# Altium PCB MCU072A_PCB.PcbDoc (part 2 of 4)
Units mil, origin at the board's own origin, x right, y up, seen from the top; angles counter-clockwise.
Board outline 2661.1 x 1953.35 mil, 8 copper layers (Top Layer, Mid-Layer 2, Mid-Layer 3, Mid-Layer 4, Mid-Layer 5, Mid-Layer 6, Mid-Layer 7, Bottom Layer), stack 61.2 mil thick; 186 components, 165 nets, 716 pads, 419 vias.
Unrouted connection lines stored in the file: 1.
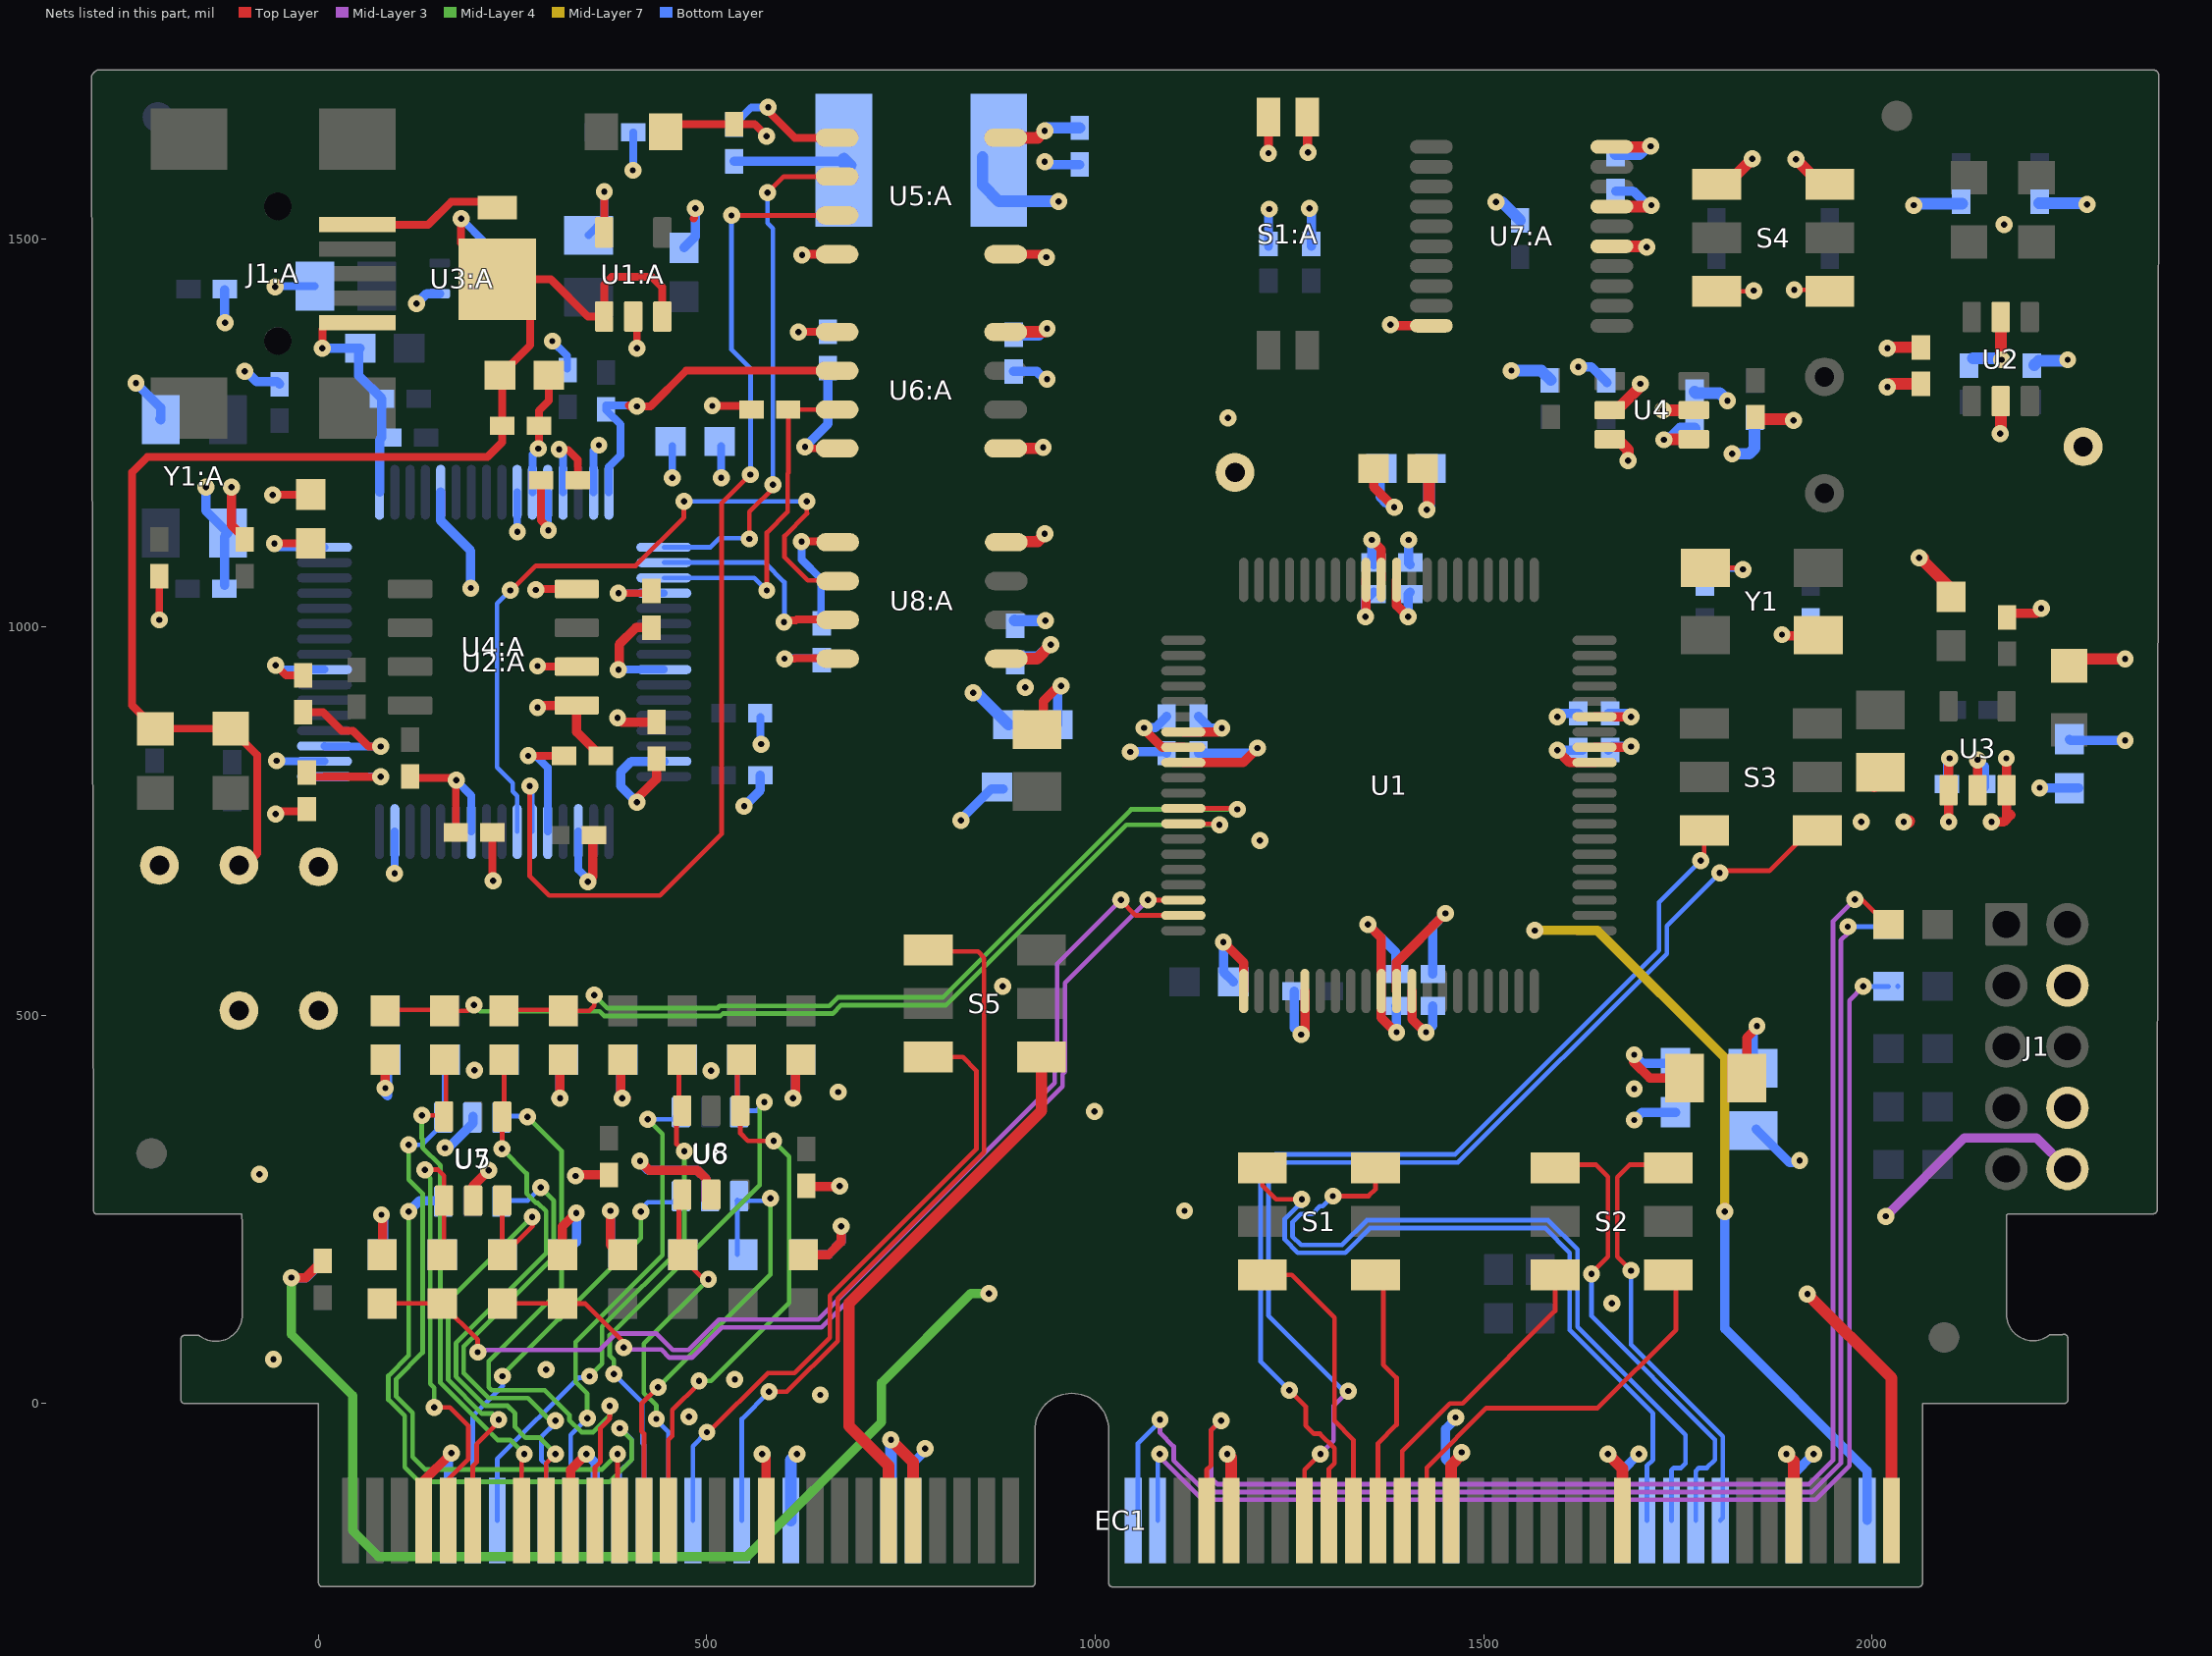
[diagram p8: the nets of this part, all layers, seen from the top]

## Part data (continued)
FID1 FID2 FID3 FID4 FID5 FID6: library part CMP-0077181-1, "Fiducial mark.  There is nothing to buy or mount.", Manufacturer=N/A
J1: library part CMP-0086568-1, "Board-To-Board Connector, TMM Series, 10 Contacts, Header, 2 mm, Through Hole, 2 Rows", Current_A=3.2A, Manufacturer=Samtec, Voltage_V=281V
J1:A: library part CMP-0054809-1, "Connector, Receptacle, USB Mini B 2.0, SMT", Color=Black, Current_A=1A, Manufacturer="Wurth Elektronik", Supplier Part Number 1=732-2109-1-ND, Voltage_V=30V
L1: library part CMP-0003363-1, "Ferrite Bead, 220 ohm @ 100 MHz, 2 A, 0805", Manufacturer=MuRata, Supplier Part Number 1=490-1054-1-ND, Value1="0.045 ohm", Value2=2A, ValueDisplayed="220 ohm"
L1:A L2:A: library part CMP-0003398-1, "Ferrite Bead, 600 ohm @ 100 MHz, 0.5 A, 0805", Manufacturer="Laird-Signal Integrity Products", Supplier Part Number 1=240-2399-1-ND, Value1="0.3 ohm", Value2=0.5A, ValueDisplayed="600 ohm"
L2: library part CMP-0003306-1, "Ferrite Bead, 60 ohm @ 100 MHz, 3 A, 0805", Manufacturer="Taiyo Yuden", Supplier Part Number 1=587-1932-1-ND, Value1="0.025 ohm", Value2=3A, ValueDisplayed="60 ohm"
LBL1: library part CMP-0003625-1, "Thermal Transfer Printable Labels, 0.650\" W x 0.200\" H - 10,000 per roll", Manufacturer=Brady, Supplier Part Number 1=97C5133
Logo1: library part CMP-0074844-1
Logo2: library part CMP-0074838-1, "Texas Instrument Corporate Signature"
Logo3: library part CMP-0074847-1, "FCC_disclaimer"
LOGO4: library part CMP-0074769-1
R1 R2: library part CMP-0026938-5, "RES, 4.7 k, 5%, 0.063 W, AEC-Q200 Grade 0, 0402", Manufacturer=Vishay-Dale, Power_W=63mW, Supplier Part Number 1=541-4.7KJCT-ND, TempCo="200 ppm/C", Tolerance_%=5%, Value2=0.063W, Value_Code=4k70, ValueDisplayed=4.7k
R1:A: library part CMP-0026962-3, "RES, 680, 5%, 0.063 W, AEC-Q200 Grade 0, 0402", Manufacturer=Vishay-Dale, Power_W=63mW, Supplier Part Number 1=541-680JCT-ND, TempCo="200 ppm/C", Tolerance_%=5%, Value2=0.063W, Value_Code=680R, ValueDisplayed=680
R2:A R4:A R8:A R15:A R16:A: library part CMP-0026825-5, "RES, 10 k, 5%, 0.063 W, AEC-Q200 Grade 0, 0402", Manufacturer=Vishay-Dale, Power_W=63mW, Supplier Part Number 1=541-10KJCT-ND, TempCo="200 ppm/C", Tolerance_%=5%, Value2=0.063W, Value_Code=10k0, ValueDisplayed=10k
R3 R4 R5 R6 R7 R8 R9 R10 R23 R24 R25 R26 R27 R28 R29 R30 R31 R32 R33 R34 R35 R36 R37 R38: library part CMP-0025697-4, "RES, 0, 5%, 0.1 W, AEC-Q200 Grade 0, 0603", Manufacturer=Vishay-Dale, Power_W=100mW, Supplier Part Number 1=541-0.0GCT-ND, TempCo="200 ppm/C", Tolerance_%=5%, Value2=0.1W, Value_Code=0000, ValueDisplayed=0
R3:A R11:A R12:A R14:A R20: library part CMP-0026822-3, "RES, 0, 5%, 0.063 W, AEC-Q200 Grade 0, 0402", Manufacturer=Vishay-Dale, Power_W=63mW, Supplier Part Number 1=541-0.0JCT-ND, TempCo="200 ppm/C", Tolerance_%=5%, Value2=0.063W, Value_Code=0000, ValueDisplayed=0
R5:A R6:A R7:A R10:A: library part CMP-0026852-3, "RES, 1.0 k, 5%, 0.063 W, AEC-Q200 Grade 0, 0402", Manufacturer=Vishay-Dale, Power_W=63mW, Supplier Part Number 1=541-1.0KJCT-ND, TempCo="200 ppm/C", Tolerance_%=5%, Value2=0.063W, Value_Code=1k00, ValueDisplayed=1.0k
R9:A R19 R21 R22: library part CMP-0026890-5, "RES, 2.2 k, 5%, 0.063 W, AEC-Q200 Grade 0, 0402", Manufacturer=Vishay-Dale, Power_W=63mW, Supplier Part Number 1=541-2.2KJCT-ND, TempCo="200 ppm/C", Tolerance_%=5%, Value2=0.063W, Value_Code=2k20, ValueDisplayed=2.2k
R11 R12: library part CMP-0026979-3, "RES, 820, 5%, 0.063 W, AEC-Q200 Grade 0, 0402", Manufacturer=Vishay-Dale, Power_W=63mW, Supplier Part Number 1=541-820JCT-ND, TempCo="200 ppm/C", Tolerance_%=5%, Value2=0.063W, Value_Code=820R, ValueDisplayed=820
R13 R14: library part CMP-0026863-2, "RES, 1.5 M, 5%, 0.063 W, AEC-Q200 Grade 0, 0402", Manufacturer=Vishay-Dale, Power_W=63mW, Supplier Part Number 1=541-1.5MJCT-ND, TempCo="200 ppm/C", Tolerance_%=5%, Value2=0.063W, Value_Code=1M50, ValueDisplayed=1.5M
R13:A: library part CMP-0026834-3, "RES, 12 k, 5%, 0.063 W, AEC-Q200 Grade 0, 0402", Manufacturer=Vishay-Dale, Power_W=63mW, Supplier Part Number 1=541-12KJCT-ND, TempCo="200 ppm/C", Tolerance_%=5%, Value2=0.063W, Value_Code=12k0, ValueDisplayed=12k
R15: library part CMP-0020442-3, "RES, 0, 5%, 0.125 W, AEC-Q200 Grade 0, 0805", Manufacturer=Vishay-Dale, Power_W=125mW, Supplier Part Number 1=541-0.0ACT-ND, TempCo="200 ppm/C", Tolerance_%=5%, Value2=0.125W, Value_Code=0000, ValueDisplayed=0
R16: library part CMP-0026944-3, "RES, 510, 5%, 0.063 W, AEC-Q200 Grade 0, 0402", Manufacturer=Vishay-Dale, Power_W=63mW, Supplier Part Number 1=541-510JCT-ND, TempCo="200 ppm/C", Tolerance_%=5%, Value2=0.063W, Value_Code=510R, ValueDisplayed=510
R17 R18: library part CMP-0026949-3, "RES, 56 k, 5%, 0.063 W, AEC-Q200 Grade 0, 0402", Manufacturer=Vishay-Dale, Power_W=63mW, Supplier Part Number 1=541-56KJCT-ND, TempCo="200 ppm/C", Tolerance_%=5%, Value2=0.063W, Value_Code=56k0, ValueDisplayed=56k
S1 S2 S4 S5: library part CMP-0002233-1, "Switch, Dual SPDT,  2 Pos, 0.1A, 6VDC, SMD", CurrentRating_mA=100A, Manufacturer="Copal Electronics", Supplier Part Number 1=CASD20JCT-ND
S1:A: library part CMP-0002230-1, "Switch, SPST, 2 Pos, 25mA, 24VDC, SMD", CurrentRating_mA=25A, Manufacturer="CTS Electrocomponents", Supplier Part Number 1=CT2182LPST-ND
S3: library part CMP-0002123-2, "SLIDE SWITCH DPDT  .1A, SMT", CurrentRating_mA=100A, Manufacturer="Copal Electronics", Supplier Part Number 1=CAS220JCT-ND
TP1 TP1:A TP2 TP2:A TP3 TP3:A TP4 TP5 TP6: library part CMP-0078143-3, "TEST POINT.  No entry in BOM.", Manufacturer=N/A
U1: library part CMP-0750188-2, "TMX320F280025CPNSR, PN0080A (LQFP-80)", Alternate Manufacturer="Texas Instruments"
U1:A: library part CMP-0073823-1, "Low-Noise, High PSRR, RF 200-mA Low-Dropout Linear Regulators, DBV0005A (SOT-23-5)", Alternate Manufacturer="Texas Instruments", Alternate PartNumber=TPS73033DBVT
U2: library part CMP-0051789-2, "Dual Buffer/Driver with Open-Drain Output, DBV0006A, LARGE T&R", F @ Nom Voltage(Max)(Mhz)=150, Generic Part Number=SN74LVC2G07, ICC @ Nom Voltage(Max)(mA)=0.01, Manufacturer="Texas Instruments", Operating Temperature Range(C)="-40 to 125", Rating=Catalog, tpd @ Nom Voltage(Max)(ns)=8.6,4.4,3.7,2.9, Voltage(Nom)(V)=1.8,2.5,3.3,5
U2:A: library part CMP-0004796-1, "Dual High Speed USB To Multipurpose UART/FIFO IC, LQFP-64", Manufacturer=FTDI, Supplier Part Number 1=768-1024-1-ND
U3: library part CMP-0036866-2, "Single Output Low Noise LDO, 400 mA, Fixed 3.3 V Output, 1.7 to 5.5 V Input, with Reverse Current Protection, 5-pin SOT-23 (DBV), -40 to 85 degC, Green (RoHS & no Sb/Br)", Alternate Manufacturer="Texas Instruments", Alternate PartNumber=TPS73633DBVT, Rating=Catalog
U3:A: library part CMP-0043096-2, "Low-Capacitance + / - 15 kV ESD-Protection Array for High-Speed Data Interfaces, 2 Channels, -40 to +85 degC, 5-pin SOT (DRL), Green (RoHS & no Sb/Br)", Breakdown Voltage(Min)(V)=11, IO Capacitance(Typ)(pF)=1.5, IO Leakage Current(nA)=1, Manufacturer="Texas Instruments"
U4: library part CMP-0067340-3, "High-Accuracy, Fixed-Threshold OV/UV Monitor, DDC0006A (SOT-23-T-6)", Alternate Manufacturer="Texas Instruments", Alternate PartNumber=TPS3702CX33DDCT
U4:A: library part CMP-0005261-2, "2K Microwire Compatible Serial EEPROM, SOIC-8", Manufacturer=Microchip, Supplier Part Number 1=93LC56C-I/SN-ND
U5 U6 U7 U8: library part CMP-0066599-1, "Automotive Low-Capacitance 4-Channel +/-15-kV ESD Protection Array for High-Speed Data Interfaces, DBV0006A (SOT-23-6)", Alternate Manufacturer="Texas Instruments"
U5:A U6:A U8:A: library part CMP-0029375-1, "25 Mbps Dual Channels, 2 / 0, Digital Isolator, 3.3 V / 5 V, -40 to +125 degC, 8-pin SOIC (D), Green (RoHS & no Sb/Br)", Insulation Rating(VRMS)=2500, Manufacturer="Texas Instruments", Rating=Catalog, Supply Voltage(s)(V)="3.3, 5"
U7:A: library part CMP-0047070-3, "Octal Buffer/Driver With 3-State OUtputs, PW0020A (TSSOP-20)", Alternate Manufacturer="Texas Instruments", Alternate PartNumber=SN74ALVC244PW, F @ Nom Voltage(Max)(Mhz)=100, Generic Part Number=SN74ALVC244, ICC @ Nom Voltage(Max)(mA)=0.024, Operating Temperature Range(C)="-40 to 85", Rating=Catalog, tpd @ Nom Voltage(Max)(ns)=4.4,3.1,2.8, Voltage(Nom)(V)=1.8,2.5,2.7,3.3
Y1: library part CMP-0080365-2, "Crystal, 20 MHz, 25 ppm, 18 pF, SMD", Frequency_Fixed=20MHz, Frequency Stability="30 ppm", Frequency Tolerance="25 ppm", Load Capacitance="18 pF", Manufacturer="ECS Inc.", Supplier Part Number 1=XC2693CT-ND
Y1:A: library part CMP-0004646-3, "Crystal, 12 MHz, 20pF, SMD", Frequency Stability=+/-50ppm, Manufacturer="ECS Inc.", PartNumber=ECS-120-20-30B-TR, Supplier Part Number 1=XC1118CT-ND
ZZ1: library part CMP-0003616-3
ZZ2: library part CMP-0077236-1
ZZ3: library part CMP-0077237-1
ZZ4: library part CMP-0077238-1

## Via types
v1: diameter 22, hole 8, Top Layer to Bottom Layer, tented both sides, 419 vias

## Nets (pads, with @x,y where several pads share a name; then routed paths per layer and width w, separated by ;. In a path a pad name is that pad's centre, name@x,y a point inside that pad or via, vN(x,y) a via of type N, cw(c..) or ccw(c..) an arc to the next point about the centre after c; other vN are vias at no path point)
3V3: C7.2 C9.1 C10.2 C20:A.1 C22:A.1 C23:A.2 C25.1 C25:A.1 EC1.119 J1.10 L1.1 L2.1 R1.1 R2.2 R11.2 R12.2 R13.2 R14.2 R15.2 R15:A.2 R16:A.2 R19.2 R21.2 R22.2 S4.1 S4.4 TP2.1 U2.5 U4.3 U4.4 U4.5 U5:A.8 U6:A.8 U7:A.20 U8:A.1 | length 3630.4
  Top Layer w12: v1(-35,162) -16.31,162 R1.1@5.31,183.62 ; L2.1@933.1,871.4 933.1,904.1 v1@949,920 ; L1.1@1839,419 1839,471 v1@1853,485
  Top Layer w15: U8:A.1@883.5,959.87 U8:A.1@885.5,959.87 ; U6:A.8@883.5,1379.87 933.87,1379.87 v1(938,1384) ; U5:A.8@883.5,1629.87 925.87,1629.87 v1(935,1639) ; U8:A.1@885.5,959 925,959 v1(943,977) ; U7:A.20@1662.34,1618 1714,1618 v1(1715,1619) ; U4.3@1662.47,1241.7 1672.3,1241.7 1686,1228 v1(1686,1214) ; v1@1731,1243 1731,1242 1731.3,1241.7 U4.4@1770.73,1241.7 ; v1(1731,1279) 1732,1279 1732.1,1279.1 U4.5@1770.73,1279.1 ; S4.1@1800.17,1569.93 1812.93,1569.93 v1(1846,1603) ; v1(1902.26,1602) 1934.33,1569.93 S4.4@1945.83,1569.93 ; v1(1917,141) 2025.31,32.69 EC1.119@2025.31,-150.67 ; R15.2@2003.24,794.76 R15.2@2003.24,809.76 ; v1(2020,1359) 2021.02,1360.02 C9.1@2063.1,1360.02 ; v1(2041,749) v1@2047.47,749 ; v1@2047.24,748.76 v1@2047.47,749 ; v1@2048.24,749.76 v1@2047.47,749 ; U2.5@2165.91,1399 2165.91,1347.09 v1@2167,1346
  Mid-Layer 3 w12: v1(2018,241) 2119,342 2211.73,342 J1.10@2251.74,302 ; J1.10@2248,302 J1.10@2251.74,302 ; J1.10@2251.84,301.89 J1.10@2251.74,302
  Mid-Layer 4 w12: v1(-35,162) -35,89 44,10 44,-164 77,-197 552,-197 725,-24 725,26.54 840.09,141.63 v1(863.24,141.63)
  Bottom Layer w12: v1(-35,162) -15.77,162 R2.2@5.51,183.28 ; C10.2@951.5,874 951.5,919.5 v1(956,924) ; R15:A.2@1223.1,1490.02 R15:A.2@1223.1,1493.02 1223.1,1537.1 v1(1224,1538) ; v1(1276,1539) 1278.1,1536.9 R16:A.2@1278.1,1493.02 R16:A.2@1278.1,1490.02 ; C7.2@1847.1,431.4 1847.1,481.1 v1(1852,486)
  Bottom Layer w15: C22:A.1@895,1376.24 927.24,1376.24 935,1384 v1(938,1384) ; C23:A.2@896.22,961.24 927.24,961.24 v1(943,977) ; v1(935,1639) 938.62,1642.62 C20:A.1@980,1642.62 ; v1(1516,1547) 1523.62,1547 R22.2@1547,1523.62 ; v1(1535.86,1330) 1574.32,1330 R19.2@1586.6,1317.72 ; C25:A.1@1670,1608.62 1700.62,1608.62 v1@1710,1618 ; v1@1731,1243 1741,1243 1753.48,1255.48 C25.1@1771.6,1255.48 ; v1(1820,1223) 1842,1223 1849,1230 R21.2@1849,1269.38 ; v1(2054,1543) 2055.86,1544.86 R11.2@2116.35,1544.86 ; R13.2@2130.23,1345.79 2165.21,1345.79 v1(2167,1344) ; R14.2@2209,1337 2214.62,1342.62 2250.62,1342.62 v1(2252,1344) ; R12.2@2215.08,1545.37 2275.63,1545.37 v1(2277,1544)
  other v1: 1986.24,748.76 910,922 1732,1241
EMU_1V8: C5:A.2 C6:A.2 C7:A.2 C8:A.2 U2:A.12 U2:A.37 U2:A.49 U2:A.64 | length 609.2
  Top Layer w10: v1(-56.72,1107.35) C5:A.2@-19.8,1107.35 ; C7:A.2@-17.19,809.68 -14.33,806.82 62.58,806.82 ; 7.72,807.23 62.17,807.23 62.58,806.82 ; v1(80,807) 62.77,807 62.58,806.82 ; v1(270,834) C8:A.2@316.38,834 ; C6:A.2@286.57,1188.84 286.57,1137.06 295.88,1127.75 v1(295.88,1124.55) v1@295.12,1125.31
  Bottom Layer w10: v1(-56.72,1107.35) -55.68,1108.38 -55.68,1105.68 -52.5,1102.5 U2:A.64@7.72,1102.5 ; U2:A.49@7.72,807.23 79.77,807.23 v1(80,807) ; v1(270,834) 280,834 295.12,818.88 U2:A.37@295.12,736.36 ; v1@295.12,1125.31 U2:A.12@295.12,1173.37
EMU_3V3: C2:A.1 C9:A.2 C10:A.2 C11:A.2 C12:A.2 C19:A.2 C21:A.2 C24:A.2 L1:A.2 L2:A.2 R1:A.1 R2:A.2 R4:A.2 R8:A.1 R10:A.1 TP2:A.1 U1:A.5 U2:A.20 U2:A.31 U2:A.42 U2:A.50 U2:A.56 U4:A.6 U4:A.8 U5:A.1 U6:A.1 U8:A.8 | length 1575.2
  Top Layer w10: v1(-55.01,950.64) -41.83,937.46 C10:A.2@-19.8,937.46 ; R8:A.1@112.18,805.44 174.32,805.44 v1(177.31,802.45) 176.73,801.87 C12:A.2@176.73,735.34 ; v1@281.2,1048.84 U4:A.8@332.48,1048.84 ; v1@282.79,948.84 U4:A.6@332.48,948.84 ; v1(367.99,1560.64) 367.79,1560.44 U1:A.5@367.79,1507.98 U1:A.5@371.93,1503.84 ; v1(386.22,1043.45) C9:A.2@425.79,1043.45 ; v1(506.99,1284.64) 552.37,1284.64 R2:A.2@552.6,1284.87 ; v1@576.5,1666.5 613.13,1629.87 U5:A.1@668.94,1629.87 ; v1(600,959) 612.6,959 613.61,960.02 ; v1@617.22,1379.87 U6:A.1@655.6,1379.87 ; v1(617.99,1379.64) 655.37,1379.64 U6:A.1@655.6,1379.87 ; U8:A.8@646.99,960.02 613.61,960.02 ; U6:A.1@655.99,1380.26 U6:A.1@655.6,1379.87 ; U8:A.8@668.94,959.87 613.76,959.87 613.61,960.02 ; U6:A.1@668.94,1379.87 U6:A.1@655.6,1379.87
  Top Layer w12: v1(410,774) 410,779 435.2,804.2 C11:A.2@435.2,830.22
  Bottom Layer w10: v1(-56.01,1437.64) -54.8,1438.84 L2:A.2@-4.8,1438.84 ; v1@-55,829 -52.91,826.91 U2:A.50@7.72,826.91 ; v1(-55.01,950.64) -49.37,945 U2:A.56@7.72,945.02 ; v1@177.31,802.26 196.69,782.88 U2:A.42@196.69,736.36 ; v1(301.07,1368.04) 320.2,1348.91 R10:A.1@320.2,1332.46 ; L1:A.2@347.57,1504.29 367.99,1524.71 v1(367.99,1560.64) ; v1(386.22,1043.45) U2:A.20@444.72,1043.45 ; v1@405.09,1588.32 R1:A.1@405.09,1636.91 ; v1(518.49,1192.13) C2:A.1@518.49,1232.64 ; C19:A.2@535,1646.62 557.38,1669 v1(579,1669) v1@580.62,1669 ; v1@568.82,854.81 R4:A.2@568.82,883.84 ; v1(600,959) 601.02,960.02 C24:A.2@646.99,960.02 ; v1(617.99,1379.64) 618.61,1380.26 C21:A.2@655.99,1380.26
  Bottom Layer w12: v1(410,774) 389.03,794.97 389.03,813.03 402.91,826.91 U2:A.31@444.72,826.91
  other v1: -53.73,827.57 570,849 281.99,949.64 279.99,1047.64 404.72,1587.95
EMU_5V0: C1:A.2 C3:A.1 D1:A.1 D3:A.2 D4:A.2 TP1:A.1 U1:A.1 U1:A.3 U3:A.1 | length 1863.2
  Top Layer w10: TP1:A.1@-91,696 -79,708 -79,834.97 D4:A.2@-113.01,868.98 -209.63,868.98 D3:A.2@-209.8,868.8 -240,899 -240,1199 -220.22,1218.78 217.5,1218.78 236.57,1237.86 C1:A.2@236.57,1258.84 236.57,1320.97 C3:A.1@233.7,1323.84 272.69,1362.83 D1:A.1@272.69,1447.05 ; v1(183.66,1525.59) 183.66,1494.38 D1:A.1@230.2,1447.84 ; D1:A.1@214.72,1468.53 251.2,1468.53 D1:A.1@272.69,1447.05 ; U1:A.3@442.6,1399.71 442.6,1437.38 429.37,1450.61 377.57,1450.61 367.79,1440.84 U1:A.1@367.79,1399.71 346.9,1399.71 299,1447.6 272.69,1447.6 D1:A.1@272.69,1447.05
  Bottom Layer w10: v1(183.66,1525.59) 214.72,1494.52 U3:A.1@214.72,1468.53
EMU_GND: C1:A.1 C2:A.2 C3:A.2 C4:A.1 C5:A.1 C6:A.1 C7:A.1 C8:A.1 C9:A.1 C10:A.1 C11:A.1 C12:A.1 C13:A.2 C14:A.1 C15:A.2 C16:A.1 C17:A.1 C18:A.1 C19:A.1 C21:A.1 C24:A.1 C26:A.2 D2:A.1 J1:A.5 R5:A.2 R11:A.2 R12:A.1 R13:A.1 R14:A.1 TP3:A.1 U1:A.2 U2:A.1 U2:A.5 U2:A.10 U2:A.11 U2:A.13 U2:A.15 U2:A.25 U2:A.35 U2:A.47 U2:A.51 U3:A.4 U4:A.5 U5:A.4 U6:A.4 U8:A.5 Y1:A.2 Y1:A.4 | length 3014.3
  Top Layer w10: v1(-205,1009) -205,1065.02 C17:A.1@-204.8,1065.22 ; v1(-59,1170) -20.14,1170 C5:A.1@-19.8,1170.34 ; v1@-46.76,762.44 C7:A.1@-17.19,762.44 ; C10:A.1@-19.8,890.22 5.94,890.22 29.9,866.26 44.29,866.26 64.55,846 v1(80,846) ; v1(5,1359) 5,1383.06 13.82,1391.87 J1:A.5@49.86,1391.87 ; v1@98.14,682.03 v1@98.27,682.15 ; C12:A.1@223.98,735.34 223.98,674.55 v1@224.87,673.65 ; v1(282.99,1229.64) 283.82,1230.46 C1:A.1@283.82,1258.84 283.82,1278.46 296.69,1291.34 C3:A.2@296.69,1323.84 ; v1(309.8,1228.54) 310.63,1227.71 321.47,1227.71 333.82,1215.37 C6:A.1@333.82,1188.84 ; R14:A.1@352,733.84 R14:A.1@352,735 ; U1:A.2@405.2,1399.71 410,1394.9 v1(410,1359) ; D2:A.1@445,1639 453.46,1647.46 C4:A.1@531.46,1647.46 ; 482.79,1525.74 483.55,1526.5 ; C4:A.1@535,1651 C4:A.1@531.46,1647.46 ; v1(577,1632) 561.54,1647.46 C4:A.1@535.2,1647.46 C4:A.1@531.46,1647.46 ; v1(621.97,1109.87) U8:A.5@668.94,1109.87 ; v1(626.37,1231.85) 628.35,1229.87 U6:A.4@668.94,1229.87
  Top Layer w12: v1(-112,1180) -112,1131 R12:A.1@-95,1114 ; v1(282,896) 284.84,898.84 U4:A.5@332.48,898.84 332.48,864.52 C8:A.1@362,835 ; v1(347,672) 353,678 R14:A.1@353,735 ; C8:A.1@363.62,834 C8:A.1@363.62,835 ; v1(385,883) 390.54,877.46 C11:A.1@435.2,877.46 ; v1(386.22,944.87) 387.08,945.72 387.08,977.2 408.99,999.12 C9:A.1@428.7,999.12 ; v1(622.61,1479.03) 623.44,1479.87 U5:A.4@668.94,1479.87
  Bottom Layer w10: U2:A.51@7.72,846.6 8.31,846 v1(80,846) ; v1@98.27,682.15 U2:A.47@98.27,736.36 ; v1@255.75,1123.73 U2:A.10@255.75,1173.37 ; U2:A.11@275.43,1173.37 275.43,1222.08 v1(282.99,1229.64) ; v1(309.8,1228.54) 314.8,1223.54 U2:A.13@314.8,1173.37 ; U2:A.35@334.49,736.36 334.49,687.51 346,676 v1@346,671 ; U2:A.15@354.17,1173.37 354.17,1227.17 v1(361,1234) ; v1@386.22,945.02 U2:A.25@444.72,945.02 ; C2:A.2@455.5,1232.64 v1(455.5,1191.9) v1@455.95,1191.44 ; v1(621.97,1109.87) 621.97,1086.64 646.99,1061.61 C24:A.1@646.99,1007.26
  Bottom Layer w12: v1(-235,1314) -203.11,1282.11 Y1:A.2@-203.11,1266.68 Y1:A.2@-204.05,1267.61 ; v1(-145,1180) -145,1149.51 Y1:A.4@-116.5,1121.01 -121.18,1116.32 C14:A.1@-121.18,1053.84 ; R11:A.2@-121.18,1433.84 -121.18,1392.42 v1(-120.28,1391.52) ; v1(-95,1329) -93,1329 -80,1316 -53.38,1316 C18:A.1@-50,1312.62 ; v1(5,1359) 5.16,1358.84 C15:A.2@53.7,1358.84 51.93,1357.07 51.93,1323.49 C16:A.1@81.57,1293.84 81.57,1243.84 78.58,1240.85 U2:A.1@78.58,1173.37 ; v1(126.39,1416.23) 139.31,1429.16 U3:A.4@155.67,1429.16 ; U2:A.5@157.32,1173.37 157.32,1136.68 196,1098 v1(196,1050) ; v1@346,671 v1(347,672) ; C13:A.2@470.54,1488.14 485,1502.6 v1(485,1539) ; C19:A.1@535,1599.38 671.13,1599.38 676.61,1604.87 678.44,1603.04 687.05,1594.43 686.35,1593.74 676.21,1594.12 C26:A.2@676.14,1594.12 ; v1(548,769) 568.82,789.82 R5:A.2@568.82,808.84 ; v1(626.37,1231.85) 655.99,1261.48 C21:A.1@655.99,1333.02
  other v1: 224.68,673.27 97.99,682.5 -55,759 256.06,1122.28
EMU_SCI-RX: U2:A.38 U5:A.3 | length 1424.5
  Top Layer w6: v1(272,795) 272,678.88 296.88,654 439.53,654 518.89,733.36 518.89,1158.86 v1(556.16,1196.13) ; v1(531.76,1529.87) U5:A.3@668.94,1529.87
  Bottom Layer w6: v1@272,794 275.43,790.57 U2:A.38@275.43,736.36 ; v1(531.76,1529.87) 531.76,1357.03 556.16,1332.63 v1(556.16,1196.13)
EMU_SCI-TX: U2:A.39 U8:A.6 | length 936.4
  Top Layer w6: v1@247,1046 279.64,1078.64 408.39,1078.64 470.5,1140.75 v1(470.5,1161.77) ; v1(628.8,1161.77) 628.8,1145.8 ; 629,1146 628.8,1145.8 ; U8:A.6@668.94,1059.87 629.88,1059.87 600,1089.74 600,1117 628.8,1145.8
  Bottom Layer w6: v1(247,1047) 230,1030 230,819 250,799 250,788 255.75,782.25 U2:A.39@255.75,736.36 ; v1@470.17,1162.09 v1(470.5,1161.77) v1(628.8,1161.77)
EMU_TCK: R3:A.1 U2:A.16 U6:A.2 | length 455.1
  Top Layer w10: v1@399.41,1285.22 400.63,1284 v1(410,1284) 427.35,1284 473.22,1329.87 U6:A.2@668.94,1329.87
  Bottom Layer w10: U2:A.16@373.86,1173.37 373.86,1206.11 388.79,1221.04 388.79,1260.75 370.2,1279.34 370.2,1285.22 408.78,1285.22 v1(410,1284)
EMU_TDI: U2:A.17 U5:A.2 | length 679.2
  Top Layer w6: v1(554.73,1113.33) 554.73,1148.05 588,1181.32 586.32,1183 v1(585,1183) ; v1(578,1559) 598.87,1579.87 U5:A.2@667.72,1579.87 U5:A.2@668.94,1579.87
  Bottom Layer w6: U2:A.17@444.72,1102.5 504.41,1102.5 516.1,1114.19 553.87,1114.19 v1(554.73,1113.33) ; v1(578,1559) 578,1520 585,1513 v1(585,1183)
EMU_TDO: U2:A.18 U8:A.7 | length 287.4
  Top Layer w10: v1(599.25,1006.09) 601.73,1008.58 614.42,1008.58 615.71,1009.87 U8:A.7@668.94,1009.87
  Bottom Layer w6: U2:A.18@444.72,1082.82 574.74,1082.82 599.9,1057.66 v1@599.9,1007.08
EMU_TMS: R2:A.1 U2:A.19 U6:A.3 | length 447.8
  Top Layer w6: v1@577.31,1046.67 577.31,1121.38 604,1148.07 604,1197.77 604.84,1198.61 604.84,1279.87 U6:A.3@668.94,1279.87
  Bottom Layer w6: U2:A.19@444.72,1063.13 560.95,1063.13 v1(577.12,1046.96)
EMU_USB_5V0: D1:A.2 J1:A.1 | length 195.6
  Top Layer w10: J1:A.1@49.86,1517.86 141.21,1517.86 170.65,1547.3 222.74,1547.3 D1:A.2@230.2,1539.84
GND: C1.2 C2.2 C3.1 C4.1 C5.1 C6.1 C7.1 C8.2 C9.2 C10.1 C11.1 C12.2 C13.2 C14.2 C15.2 C16.2 C17.2 C18.2 C19.2 C20.2 C20:A.2 C21.1 C22.1 C22:A.2 C23.1 C23:A.1 C24.1 C25.2 C25:A.2 C26.2 C26:A.1 C27.2 C28.1 C29.2 C30.2 C31.2 C32.2 C33.2 C34.2 C35.2 C36.2 C37.2 C38.2 C39.2 C40.2 C41.2 C42.2 C43.2 C44.2 D3.1 EC1.7 EC1.10 EC1.19 EC1.22 EC1.35 EC1.38 EC1.46 EC1.47 EC1.65 EC1.83 EC1.97 EC1.111 J1.4 J1.8 S1:A.3 S1:A.4 S4.3 S4.6 TP4.1 U1.9 U1.21 U1.25 U1.30 U1.55 U1.70 U2.2 U3.2 U4.2 U5.2 U5:A.5 U6.2 U6:A.5 U7.2 U7:A.10 U7:A.15 U7:A.17 U8.2 U8:A.4 Y1.2 Y1.4 | length 5460.8
  Top Layer w6: Y1.2@1785.5,1076.13 1831.87,1076.13 v1(1834,1074) ; S4.3@1800.17,1432.13 1847.13,1432.13 v1(1848,1433) ; v1(1900,1434) 1943.97,1434 S4.6@1945.83,1432.13
  Top Layer w12: v1(81,243) 82.9,241.1 C29.2@82.9,192.1 ; v1(86,406) C31.2@86,442.5 ; EC1.7@135.55,-150.67 135.55,-99.45 v1(171,-64) ; U5.2@199.1,261.27 199.1,280.1 v1(219,300) v1@220,299 ; v1(311,393) C32.2@311,445.01 ; C30.2@314.1,191.9 C30.2@314.1,194.9 ; C30.2@316,193 C30.2@314.1,194.9 ; EC1.19@324.53,-150.67 324.53,-85.47 v1(345,-65) ; v1@327,291 330.38,294.38 C27.2@376,294.38 ; v1@333,247 314.1,228.1 C30.2@314.1,194.9 ; v1(376,248) 376,204 C39.2@387,193 ; C41.2@389.1,443.9 389.1,399.9 v1@396,393 ; v1(414,312) 426,300 488,300 499.1,288.9 U8.2@499.1,261.27 ; v1(571,-65) 576.49,-70.49 EC1.35@576.49,-150.67 ; v1(611,393) 614.1,396.1 C36.2@614.1,443.9 ; C37.2@624,191.5 656.5,191.5 673,208 v1(673,228) ; C26.2@626,279.38 664.62,279.38 665.25,280 v1(671,280) ; U5:A.5@883.5,1479.87 933.13,1479.87 v1(937,1476) ; U1.9@1113.45,825.29 1190.29,825.29 v1(1209,844) ; v1(1165,594) 1191.2,567.8 U1.21@1191.2,531 ; v1(1223,1610) 1223.1,1610.1 S1:A.4@1223.1,1656.4 ; v1(1265,475) 1269.94,479.94 U1.25@1269.94,531 ; S1:A.3@1273.1,1656.4 1273.1,1611.9 v1(1274,1611) ; v1(1351,617) 1368.37,599.63 U1.30@1368.37,531 1368.37,496.63 1387,478 v1(1388.06,478) ; v1(1380,1389) 1381.32,1387.68 U7:A.10@1430.05,1387.68 ; U1.70@1388.06,1060.53 1388.06,1027.94 v1(1403,1013) ; U1.55@1642.98,884.35 v1(1690,884.35) ; v1@1882.64,988.52 Y1.4@1931.17,988.52 ; U3.2@2136,789.63 v1(2136,828.76) ; C21.1@2176,1017.39 2211.62,1017.39 v1(2218,1023.76)
  Top Layer w15: v1(737,-47) 765.47,-75.47 EC1.47@765.47,-150.67 ; U8:A.4@883.5,1109.87 925.87,1109.87 935,1119 v1(935,1120) ; U6:A.5@883.5,1229.87 931.87,1229.87 v1(933,1231) ; v1(1170,-65) 1174.92,-69.92 EC1.65@1174.92,-150.67 ; v1@1429.6,1159.6 C2.2@1429.6,1191.4 ; EC1.83@1458,-144.29 1458,-80 v1@1473,-64 ; v1(1660,-65) 1678.86,-83.86 EC1.97@1678.86,-150.67 ; U7:A.15@1662.34,1490.05 v1@1708.95,1490.05 ; U7:A.17@1662.34,1541.23 1714.23,1541.23 v1(1716,1543) ; U4.2@1662.47,1279.1 1671.65,1279.1 1702,1309.45 v1(1702,1313) ; C24.1@1854,1267.38 v1@1897.62,1267.38 ; v1(1890,-65) 1899.33,-74.33 EC1.111@1899.33,-150.67 ; v1(2020,1309) 2023.78,1312.78 C9.2@2063.1,1312.78 ; v1@2066,1088.76 2066,1085.26 C22.1@2106,1045.26 ; v1(2165,1249) 2165.91,1249.91 U2.2@2165.91,1290.73 ; D3.1@2254,949.98 2262.78,958.76 v1(2326,958.76)
  Bottom Layer w6: C18.2@1785,1055.62 1803.38,1074 v1(1834,1074) ; v1@1887,989 1901.62,989 C17.2@1921,1008.38 ; v1(1900,1434) v1@1900.62,1434.62
  Bottom Layer w12: v1(81,243) 84.1,239.9 C43.2@84.1,191.9 ; v1(86,406) 86,399.2 89.1,396.1 C34.2@89.1,443.9 ; v1(163,329) 165.63,329 v1@166.31,329.69 ; v1@167,329 199.1,361.1 U7.2@199.1,369.53 ; EC1.10@167.05,-150.67 167.05,-67.95 v1(171,-64) ; v1@306,393 v1@311,398 ; v1(311,393) v1@311,398 ; C33.2@311,445.01 v1@311,398 ; C42.2@315,191 332,208 v1(332,245) ; v1(345,-65) 356.02,-76.02 EC1.22@356.02,-150.67 ; v1(376,248) 376,205 C40.2@392,189 ; C44.2@389.1,443.9 389.1,394.9 v1(391,393) ; v1@412,313 425,300 488,300 499.1,288.9 U6.2@499.1,261.27 ; v1(611,393) 614.1,396.1 C38.2@614.1,443.9 ; C35.2@614.1,191.9 C35.2@623.93,191.9 ; C35.2@623.93,191.5 656.5,191.5 673,208 v1(673,228) ; v1(827,751) 827,752 866.4,791.4 C11.1@881.6,791.4 ; v1@843,914 v1(843,915) ; C22:A.2@895,1329 925,1329 935,1319 v1(938,1319) ; v1(935,1599) 938.62,1595.38 C20:A.2@980,1595.38 ; v1(1045,839) 1090.38,839 C6.1@1092,837.38 ; C12.2@1133,837.38 1202.38,837.38 v1(1209,844) ; v1(1165,594) 1165,555.99 C28.1@1177.99,543 ; C16.2@1256.38,531 1256.38,483.62 v1(1265,475) ; v1(1351,617) 1387.38,580.62 C5.1@1387.38,553 ; C13.2@1387.38,512 1388.06,511.32 v1(1388.06,478) ; v1(1403,1013) 1403,1042.38 C15.2@1405.62,1045 ; v1(1403.62,1112) 1403.62,1082 C3.1@1405.62,1080 ; v1(1595,884.35) 1599.28,888.62 C14.2@1622,888.62 ; v1(1622,1335) 1638.62,1335 C23.1@1659,1314.62 ; C4.1@1660.98,888.62 1685.72,888.62 v1(1690,884.35) ; C25:A.2@1670,1561.38 1692.62,1561.38 1711,1543 v1(1716,1543) ; v1(1694,365) 1703.9,374.9 C8.2@1747.1,374.9 ; C7.1@1851,353 1894,310 v1@1907,310 ; v1(2136,828.76) 2144.62,820.14 C20.2@2144.62,793.76 ; C19.2@2254,855.26 2255.5,853.76 v1(2326,853.76)
  Bottom Layer w15: EC1.38@607.99,-150.67 607.99,-73.01 v1(616,-65) ; EC1.46@737,-146.64 v1(737,-47) ; v1@840,914 843,914 848.5,914 C10.1@888.5,874 ; C26:A.1@854.96,1604.87 854.96,1569.04 876,1548 v1(953,1548) ; C23:A.1@896.22,1008.49 896.71,1008 v1(936,1008) ; v1@1428,1151 1430,1153 C1.2@1430,1196 ; C25.2@1771.6,1302.72 1773.32,1301 1804,1301 v1(1814,1291)
  other v1: 1472,-63 477,-17.26 646,11 536,31 293,43.63 -58,57 1665.14,129 1115,248 331,293 -76,295 1907,313 999,376 669,401 505.64,428.5 201,429 881,537 1212,725 1884.16,990 2061,1088.76 1427,1151 1899,1266 1171,1269 1710,1489 2170,1518
HSEC_5V0: C19.1 C20.1 EC1.48 EC1.84 EC1.98 EC1.112 TP1.1 U3.1 U3.3 | length 713.5
  Top Layer w12: v1@2099,752.76 2098.6,753.17 2098.6,831.36 2099.2,830.76 v1(2100,830.76) ; v1(2154,748.76) 2169.8,748.76 2178.8,757.76 2176.8,759.76 2173.4,756.36 2173.4,829.36 v1@2172,830.76
  Bottom Layer w12: EC1.48@765.47,-150.67 765.47,-76.53 781,-61 v1(781,-58.1) ; EC1.84@1458.38,-150.67 1458.38,-79.08 1451,-71.7 1451,-33 1464,-20 v1(1464,-18) ; EC1.98@1678.86,-150.67 1678.86,-86.14 v1(1700,-65) ; EC1.112@1899.33,-150.67 1899.33,-90.67 v1(1925,-65) ; C20.1@2097.38,793.76 2097.38,830.14 2098.76,828.76 2100,830.01 v1(2100,830.76) ; v1(2216,792.76) 2253.5,792.76 C19.1@2254,792.27 C19.1@2266,792.27
  other v1: 2099,748.76 2173,830.76
HSEC_A0/C15: EC1.9 R23.2 U5.1 | length 636.9
  Top Layer w6: v1(137,301) 154,301 161.7,293.3 161.7,203.1 166,198.8 R23.2@159.1,191.9 ; v1(149,-5) 169,-5 193,-29 193,-71.46 167.05,-97.41 EC1.9@167.05,-150.67
  Mid-Layer 4 w6: v1(137,301) 133,301 144,290 144,25.29 149,20.29 v1(149,-5)
HSEC_A1: EC1.11 R24.2 U5.3 | length 620.4
  Top Layer w6: EC1.11@198.54,-150.67 198.54,-81 203.54,-76 203.54,-52.46 v1@237,-19 ; R24.2@236,193 236.5,193.5 U5.3@236.5,261.27 ; R24.2@239.1,191.9 276,228.8 275,229.8 v1(275,240)
  Mid-Layer 4 w6: v1(232,-21) 224,-13 210.57,-13 167,30.57 167,132 v1(275,240)
HSEC_A2/C9: EC1.15 R25.2 U5.6 | length 690.6
  Top Layer w6: v1(133,371) 160.23,371 U5.6@161.7,369.53 ; U5.6@162,371 164.1,373.1 R25.2@164.1,443.9 ; EC1.15@261.53,-150.67 261.53,-68.47 v1(265,-65)
  Mid-Layer 4 w6: v1(133,371) 133,341.46 134,340.46 134,329.46 157,306.46 157,26.43 230.43,-47 247,-47 v1(265,-65)
HSEC_A3/C5/VDAC: EC1.17 R26.2 U5.4 | length 755
  Top Layer w6: v1(236,328) 236.5,328.5 U5.4@236.5,369.53 ; U5.4@239.1,368.1 R26.2@239.1,443.9 ; EC1.17@293.03,-150.67 293.03,-76.97 v1(305,-65)
  Mid-Layer 4 w6: v1(236,328) 268,296 268,270.54 280.54,258 282.46,258 293,247.46 293,193.6 177,77.6 177,34.72 214.72,-3 243.46,-3 253,-12.54 253,-30.46 266.54,-44 285,-44 v1@306,-65
HSEC_A4/C14: EC1.21 R27.2 U7.3 | length 883.7
  Top Layer w6: EC1.21@356.02,-150.67 356.02,-81.98 363,-75 363,-31.54 375,-19.54 v1(375,-3)
  Mid-Layer 4 w6: v1(269,369) 313,325 313,148.54 219,54.54 219,21 223,17 291.46,17 323,-14.54 323,-21.46 338.54,-37 353.46,-37 375,-15.46 v1(375,-3)
  Bottom Layer w6: R27.2@239.1,443.9 239.1,439.1 239.1,373.1 236,370 v1@268,370
  Bottom Layer w12: R27.2@236.5,436.5 239.1,439.1 241,441 R27.2@241,445
HSEC_A5/C2: EC1.23 R28.2 U7.1 | length 936.9
  Top Layer w6: v1(385,-65) 385,-148.15 EC1.23@387.52,-150.67
  Mid-Layer 4 w6: v1(116,333) 116,288.46 134,270.46 134,65.46 100,31.46 100,9 121,-12 121,-69 137,-85 365,-85 v1(385,-65)
  Bottom Layer w6: v1@117,333 133,333 161.7,361.7 R28.2@161.7,439.3
  Bottom Layer w12: R28.2@159,443 159,442 R28.2@161.7,439.3
HSEC_A6: EC1.25 R29.2 U6.1 | length 604.3
  Top Layer w6: EC1.25@419.01,-150.67 419.01,-39.01 416,-36 416,0 v1(437,21) v1@438,22
  Mid-Layer 4 w6: v1@437,29 v1(437,21) 582,166 v1(582,264)
  Bottom Layer w6: U6.1@538.2,261 539.1,261.9 U6.1@539.1,261 ; R29.2@539.1,191.9 U6.1@539.1,261 ; v1@578,261 U6.1@539.1,261
HSEC_A7/C3: EC1.27 R30.2 U8.4 | length 713.4
  Top Layer w6: EC1.27@450.51,-150.67 450.51,-47 455.51,-42 455.51,-8.49 490,26 v1(490,29) ; U8.4@539.1,377 R30.2@539.1,443.9 ; U8.4@543.04,377 543.04,347.96 553,338 v1(586,338)
  Mid-Layer 4 w6: v1(490,29) 505.46,29 606,129.54 606,318 v1(586,338)
HSEC_A9/C8: EC1.26 R32.2 U6.6 | length 754.8
  Mid-Layer 4 w6: v1(380.14,38) 380.14,56 375,61.14 375,88 568,281 568,382 v1(574,388)
  Bottom Layer w6: v1(380.14,38) 404.57,13.57 417,1.14 417,-51 419.01,-53.01 EC1.26@419.01,-150.67 ; U6.6@536.5,369.53 U6.6@538.48,371.52 ; R32.2@539.1,434.1 539.1,375.1 537,373 U6.6@538.48,371.52 ; v1@574,387 564,377 543.97,377 U6.6@538.48,371.52
  Bottom Layer w12: R32.2@539.1,434.1 541,436 R32.2@541,440
HSEC_A10/C10: EC1.28 R33.2 U8.1 | length 489
  Top Layer w6: U8.1@461,262.8 464.1,265.9 464.1,191.9 496,160 v1(502,160)
  Top Layer w12: R33.2@461,193 R33.2@461.7,193.7
  Mid-Layer 4 w6: v1(435,-20) 435,-2.46 419,13.54 419,77 v1(502,160)
  Bottom Layer w6: v1@434,-20 450.51,-36.51 EC1.28@450.51,-150.67
HSEC_A11/C0: EC1.12 R34.2 U6.3 | length 613.6
  Mid-Layer 4 w6: v1(237,35) 237,36.46 308.54,108 310,108 415,213 v1(415,247)
  Bottom Layer w6: EC1.12@198.54,-150.67 198.54,-16.46 237,22 v1(237,35) ; v1@414,249 424,259 456,259 458.9,261.9 464.1,261.9 R34.2@464.1,191.9
HSEC_A12/C1: EC1.14 R35.2 U8.6 | length 706.4
  Top Layer w6: R35.2@464.1,443.9 464.1,371.1 461,368 461,334 v1@467,328
  Mid-Layer 4 w6: v1(349,35) 365,51 365,99 471,205 v1(471,325)
  Bottom Layer w6: EC1.14@230.04,-150.67 230.04,-71.51 334.54,33 351,33 v1(349,35)
HSEC_A14/C4: EC1.18 R36.2 U7.4 | length 711.5
  Mid-Layer 4 w6: v1(286,278) 303,261 303,188.91 198.09,84 197.54,84 187,73.46 187,38.86 218.86,7 269.4,7 301.4,-25 304.4,-22 v1(305,-22)
  Bottom Layer w6: R36.2@236,193 236.5,193.5 236.5,197.5 236.5,261.27 269.27,261.27 v1(286,278) v1@287,279 ; EC1.18@293.03,-150.67 293.03,-78.49 287,-72.46 287,-43 305,-25 v1(305,-22)
  Bottom Layer w12: R36.2@236.5,197.5 R36.2@241,193
HSEC_A15/C7: EC1.24 R37.2 U7.6 | length 958.4
  Mid-Layer 3 w6: v1@386,-32 v1(388,-32)
  Mid-Layer 4 w6: v1(116,247) 116,61.6 90,35.6 90,4.86 111,-16.14 111,-82 130,-101 374.46,-101 403,-72.46 403,-47 v1(388,-32)
  Bottom Layer w6: U7.6@156.73,261.27 160,258 159.1,257.1 R37.2@159.1,191.9 ; EC1.24@387.52,-150.67 387.52,-87.94 403,-72.46 403,-46 389,-32 v1(388,-32)
  Bottom Layer w12: v1(116,247) 130.27,261.27 U7.6@156.73,261.27
HSEC_C6: EC1.20 R38.2 U6.4 | length 691.8
  Mid-Layer 4 w6: v1(346,-19) 346,12.54 331,27.54 331,79.14 442.98,191.12 442.98,347.02 v1(424,366)
  Bottom Layer w6: EC1.20@324.53,-150.67 324.53,-40.47 v1(346,-19) ; EC1.20@327,-150.67 EC1.20@329.53,-150.67 ; v1@434,366 456,366 464.1,374.1 R38.2@464.1,443.9
HSEC_GPIO11: EC1.63 R5.1 | length 1828.8
  Top Layer w6: EC1.63@1143.42,-150.67 1143.42,-85.58 1149,-80 1149,-35 v1(1162,-22) ; v1(1978,649) 1987,649 2019,617 R5.1@2021.5,617 R5.1@2027.01,617
  Mid-Layer 3 w6: v1(1162,-22) 1149,-35 1149,-96 1157,-104 1919,-104 1950,-73 1950,621 v1(1978,649)
HSEC_GPIO12: EC1.58 R3.1 | length 1849.5
  Mid-Layer 3 w6: v1(1083.43,-21) 1083.43,-37.89 1101,-55.46 1101,-73.06 1141.94,-114 1923.14,-114 1960,-77.14 1960,596.5 1969,605.5 v1(1969,614)
  Bottom Layer w6: EC1.58@1055,-144.61 1055,-51.43 v1@1085.43,-21 ; v1(1969,614) 2026.5,614 2031.5,619 2033.5,617 R3.1@2033,617
HSEC_GPIO13: EC1.60 R4.1 | length 1678.3
  Mid-Layer 3 w6: v1(1083,-65) 1083,-69.2 1137.8,-124 1927.28,-124 1971,-80.28 1971,519 v1(1989,537)
  Bottom Layer w6: EC1.60@1080.43,-150.67 1080.43,-69.57 v1@1085,-65 ; v1(1989,537) R4.1@2021.5,537 ; R4.1@2033.5,537 R4.1@2033.5,537.5
HSEC_GPIO18: EC1.71 S3.6 | length 1427.4
  Top Layer w6: EC1.71@1269.41,-150.67 1269.41,-85.59 v1(1290,-65) ; v1(1804,683) 1807,686 1868,686 1919.65,737.65 S3.6@1929.83,737.65
  Mid-Layer 3 w6: v1(1290,-65) 1307,-48 1307,-3 v1(1326,16)
  Bottom Layer w6: v1(1326,16) 1320,16 1223,113 1223,296.64 1236.5,310.14 1467,310.14 1736,579.14 1736,615 v1(1804,683)
HSEC_GPIO19: EC1.73 S3.3 | length 1320.7
  Top Layer w6: v1(1250,17) 1271,-4 1271,-28.46 1281.54,-39 1289.46,-39 1308,-57.54 1308,-77 1300.9,-84.1 EC1.73@1300.9,-150.67 ; v1(1779.5,699) 1784.17,703.67 S3.3@1784.17,737.65 S3.3@1797.35,737.65
  Bottom Layer w6: v1(1250,17) 1213,54 1213,302 1231.75,320.75 1463.47,320.75 1726,583.28 1726,645.5 v1(1779.5,699)
HSEC_pin30: EC1.30 S5.4 | length 821.1
  Top Layer w6: v1(500,-37) 502.54,-37 578.54,39 612.86,39 658.5,84.64 658.5,139.15 847,327.65 847,428.5 829.4,446.1 S5.4@785.17,446.1
  Bottom Layer w6: EC1.30@482.01,-150.67 482.01,-54.99 v1(500,-37)
HSEC_pin34: EC1.34 S5.6 | length 943.3
  Top Layer w6: v1(580,15) 603,15 668.5,80.5 668.5,135.01 857,323.51 857,574 849,582 787.06,582 S5.6@785.17,583.9
  Bottom Layer w6: EC1.34@545,-150.67 545,-20 v1(580,15)
HSEC_PIN75: EC1.75 S1.3 | length 386.9
  Top Layer w6: S1.3@1215.27,165.57 1253,165.57 1308,110.57 1308,-22.46 1332.4,-46.86 EC1.75@1332.4,-150.67
HSEC_PIN77: EC1.77 S1.6 | length 333.3
  Top Layer w6: EC1.77@1363.9,-150.67 1363.9,-51.56 1388,-27.46 1388,33 1370.93,50.07 S1.6@1370.93,165.57
HSEC_PIN79: EC1.79 S2.3 | length 407.4
  Top Layer w6: EC1.79@1395.39,-150.67 1395.39,-61.15 1456.54,0 1473,0 1592.17,119.17 S2.3@1592.17,165.57
HSEC_PIN81: EC1.81 S2.6 | length 530.7
  Top Layer w6: EC1.81@1426.89,-150.67 1426.89,-82.66 1503.54,-6 1647,-6 1747.83,94.83 S2.6@1747.83,163.1
HSEC_PIN100: EC1.100 S1.1 | length 937.8
  Top Layer w6: S1.1@1215.27,303.36 1215.27,280.73 1233,263 v1(1266,263)
  Bottom Layer w6: v1(1266,263) 1266,254 1260.4,254 1244,237.6 1244,211 1261,194 1322,194 1354,226 1579,226 1611,194 1611,94.46 1718,-12.54 1718,-72.46 1710.35,-80.1 EC1.100@1710.35,-150.67
HSEC_PIN102: EC1.102 S1.4 | length 990.2
  Top Layer w6: v1(1306,267) 1352,267 1360.93,275.93 S1.4@1360.93,303.36
  Bottom Layer w6: v1(1306,267) 1293,254 1289.4,254 1279.4,244 1264.54,244 1254,233.46 1254,215.14 1265.14,204 1317.86,204 1349.86,236 1583.14,236 1621,198.14 1621,98.6 1760,-40.4 1760,-77.31 1754.31,-83 1745,-83 1741.85,-86.15 EC1.102@1741.85,-150.67
HSEC_pin104: EC1.104 S2.1 | length 606.5
  Top Layer w6: S2.1@1592.17,307.3 1644.7,307.3 1660,292 1660,189 v1@1639,168
  Bottom Layer w6: v1(1639,167) 1639,112.5 1798,-46.5 1798,-72.46 1787.46,-83 1777.35,-83 1773.35,-87 EC1.104@1773.35,-150.67
HSEC_pin106: EC1.106 S2.4 | length 572.2
  Top Layer w6: v1(1690,171) 1672,189 1672,291.46 1687.84,307.3 S2.4@1737.83,307.3
  Bottom Layer w6: v1(1690,171) 1690,75.64 1808,-42.36 1808,-147.51 EC1.106@1804.84,-150.67
HSEC_VREFHI: EC1.45 S5.1 | length 720.5
  Top Layer w15: EC1.45@733.98,-150.67 733.98,-80.08 683,-29.1 683,129 930.83,376.83 S5.1@930.83,446.1
MCU_1V2: C1.1 C2.1 C3.2 C4.2 C5.2 C6.2 EC1.118 TP3.1 U1.8 U1.31 U1.53 U1.71 | length 1562.5
  Top Layer w12: v1@1058.28,869.67 1058.61,870 v1@1061,870 ; v1(1063,870) v1@1061,870 ; U1.8@1113.45,844.98 1086.02,844.98 v1@1061,870 ; v1(1356,1112) 1368.37,1099.63 U1.71@1368.37,1060.53 ; C2.1@1358.5,1204 1358.5,1180.5 v1(1385,1154) ; U1.31@1388.06,531 1388.06,568.06 v1(1451,631) ; U1.53@1642.98,844.98 1688.98,844.98 v1(1690,846)
  Mid-Layer 7 w12: v1(1566,609) 1646.63,609 1810.74,444.89 v1(1810.74,247)
  Bottom Layer w12: v1(1063,870) 1077.38,870 C6.2@1092,884.62 ; v1(1356,1112) 1356,1082.38 C3.2@1358.38,1080 ; C1.1@1366.6,1191.4 1366.6,1167.4 1375,1159 ; C5.2@1434.62,553 1434.62,614.62 v1(1451,631) ; C4.2@1660.98,841.38 1665.6,846 v1(1690,846) ; v1(1810.74,247) 1810.74,96.26 1993.82,-86.82 EC1.118@1993.82,-150.67
MCU_3V3: C8.1 C12.1 C13.1 C14.1 C15.1 L1.2 U1.7 U1.32 U1.52 U1.72 | length 500.1
  Top Layer w12: U1.7@1113.45,864.66 1158.04,864.66 v1(1163,869.62) ; v1(1347.77,1013) 1348.69,1013.91 U1.72@1348.69,1060.53 ; U1.32@1407.74,531 1407.74,494.88 1424.62,478 v1(1426,478) ; v1(1595,841) 1610.71,825.29 U1.52@1642.98,825.29 ; v1@1693,440 v1@1694,441 ; v1(1694,449) v1@1694,441 ; L1.2@1759,419 1714,419 1694,439 v1@1694,441
  Bottom Layer w12: C12.1@1133,884.62 1148,869.62 v1(1163,869.62) ; v1(1347.77,1013) 1347.77,1034.39 C15.1@1358.38,1045 ; v1(1426,478) 1434.62,486.62 C13.1@1434.62,512 ; v1(1595,841) 1626.62,841 C14.1@1627,841.38 ; v1(1694,449) 1705.1,437.9 C8.1@1747.1,437.9
  other v1: 1694,405
MCU_A0/C15: C29.1 R23.1 U1.19 | length 1428.8
  Top Layer w6: C29.1@84.1,128.9 159.1,128.9 159.1,127.9 205,82 v1(205,66) ; v1@1032.3,648.13 1051.99,628.44 U1.19@1113.45,628.44
  Mid-Layer 3 w6: v1@206,66 209,69 362,69 383,90 435.14,90 456.14,69 476.46,69 515.46,108 643.43,108 948,412.57 948,428.33 951,431.33 951,566.5 v1(1033,648.5) v1@1024.5,648.5
MCU_A1: C30.1 R24.1 U1.18 | length 1222.4
  Top Layer w6: R24.1@239.1,128.9 C30.1@310,128.9 ; C30.1@314.29,128.5 343.36,128.5 393,78.87 v1(393,72) ; v1(1067.92,648.5) 1068.3,648.13 U1.18@1113.45,648.13
  Mid-Layer 3 w6: v1@394,72 396.54,69.46 441.54,69.46 452,59 480.6,59 519.6,98 647.57,98 958,408.43 958,424.19 961,427.19 961,541.58 v1(1067.92,648.5)
MCU_A2/C9: C31.1 R25.1 U1.13 | length 1229.4
  Top Layer w6: C31.1@89.1,506.9 R25.1@162.9,506.9 ; R25.1@162.43,505.5 192.5,505.5 v1(200,513) ; U1.13@1113.45,746.55 1158.45,746.55 v1(1160,745)
  Mid-Layer 4 w6: v1(200,513) 208,505 361.86,505 367.86,499 513.6,499 517.6,499 520.6,502 662,502 673,513 808.28,513 1040.28,745 v1(1160,745)
MCU_A3/C5/VDAC: C32.1 R26.1 U1.12 | length 1143.7
  Top Layer w6: R26.1@239.1,506.89 C32.1@315.29,506.89 ; C32.1@315.29,505.5 348.5,505.5 355,512 v1(355,526) ; U1.12@1113.45,766.24 1181.76,766.24 v1(1183,765)
  Mid-Layer 4 w6: v1(355,526) 372,509 513.46,509 516.46,512 657.86,512 668.86,523 804.14,523 1046.14,765 v1(1183,765)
